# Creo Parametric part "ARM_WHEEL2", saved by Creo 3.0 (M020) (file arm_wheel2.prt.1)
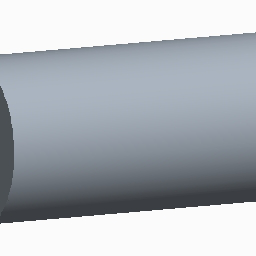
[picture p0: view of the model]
Units: millimeter Newton Second (mmNs); MM, TONNE, SECS

Created from: MMNS_PART_SOLID.PRT

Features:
  1. datum plane "RIGHT"
  2. datum plane "TOP"
  3. datum plane "FRONT"
  4. coordinate system
  5. sketch "Sketch 1"
  6. extrusion "Extrude 1"

Surfaces: 5 plane, 2 cylinder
